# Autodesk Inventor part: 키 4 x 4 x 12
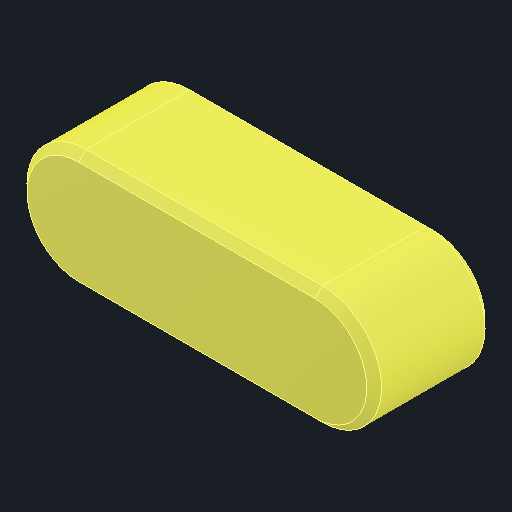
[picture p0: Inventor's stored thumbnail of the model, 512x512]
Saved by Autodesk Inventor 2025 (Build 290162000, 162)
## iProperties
Created: 2025-08
Part Number: 키 4 x 4 x 12
Material: 강철, 연강
Description: 키 및 해당 키홈
Document SubType Name: Modeling
Designer: infra012
Density: 7.85 g/cm^3
Appearance: 기본값
Author: jhkim
Sending System: Autodesk Inventor 2026
Preprocessor: ST-DEVELOPER v20.1
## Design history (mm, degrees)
sketch "스케치1"
  geometry: 1 further point
  constraints: 1 other
feature "Solid1"
node "솔리드1"
